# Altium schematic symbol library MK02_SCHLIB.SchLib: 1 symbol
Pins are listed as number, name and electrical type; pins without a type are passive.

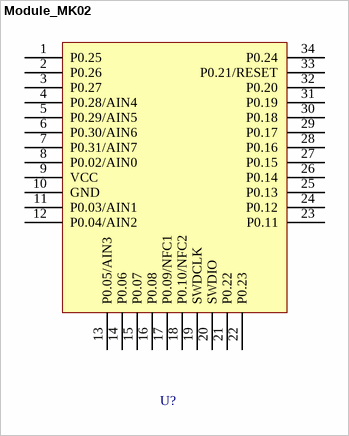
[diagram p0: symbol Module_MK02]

## Module_MK02
designator U?, comment MK02  (value not drawn)
footprint PCB_MK02_05_06 (21.0*13.8mm)
pins: 1 P0.25, 2 P0.26, 3 P0.27, 4 P0.28/AIN4, 5 P0.29/AIN5, 6 P0.30/AIN6, 7 P0.31/AIN7, 8 P0.02/AIN0, 9 VCC, 10 GND, 11 P0.03/AIN1, 12 P0.04/AIN2, 13 P0.05/AIN3, 14 P0.06, 15 P0.07, 16 P0.08, 17 P0.09/NFC1, 18 P0.10/NFC2, 19 SWDCLK, 20 SWDIO, 21 P0.22, 22 P0.23, 23 P0.11, 24 P0.12, 25 P0.13, 26 P0.14, 27 P0.15, 28 P0.16, 29 P0.17, 30 P0.18, 31 P0.19, 32 P0.20, 33 P0.21/RESET, 34 P0.24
